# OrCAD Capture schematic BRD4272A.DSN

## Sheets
1 02: RF & Power: size A3; title: FG25 470 MHz 16 dBm Radio Board; rev: A02; company: Silicon Labs; note: BRD4272A
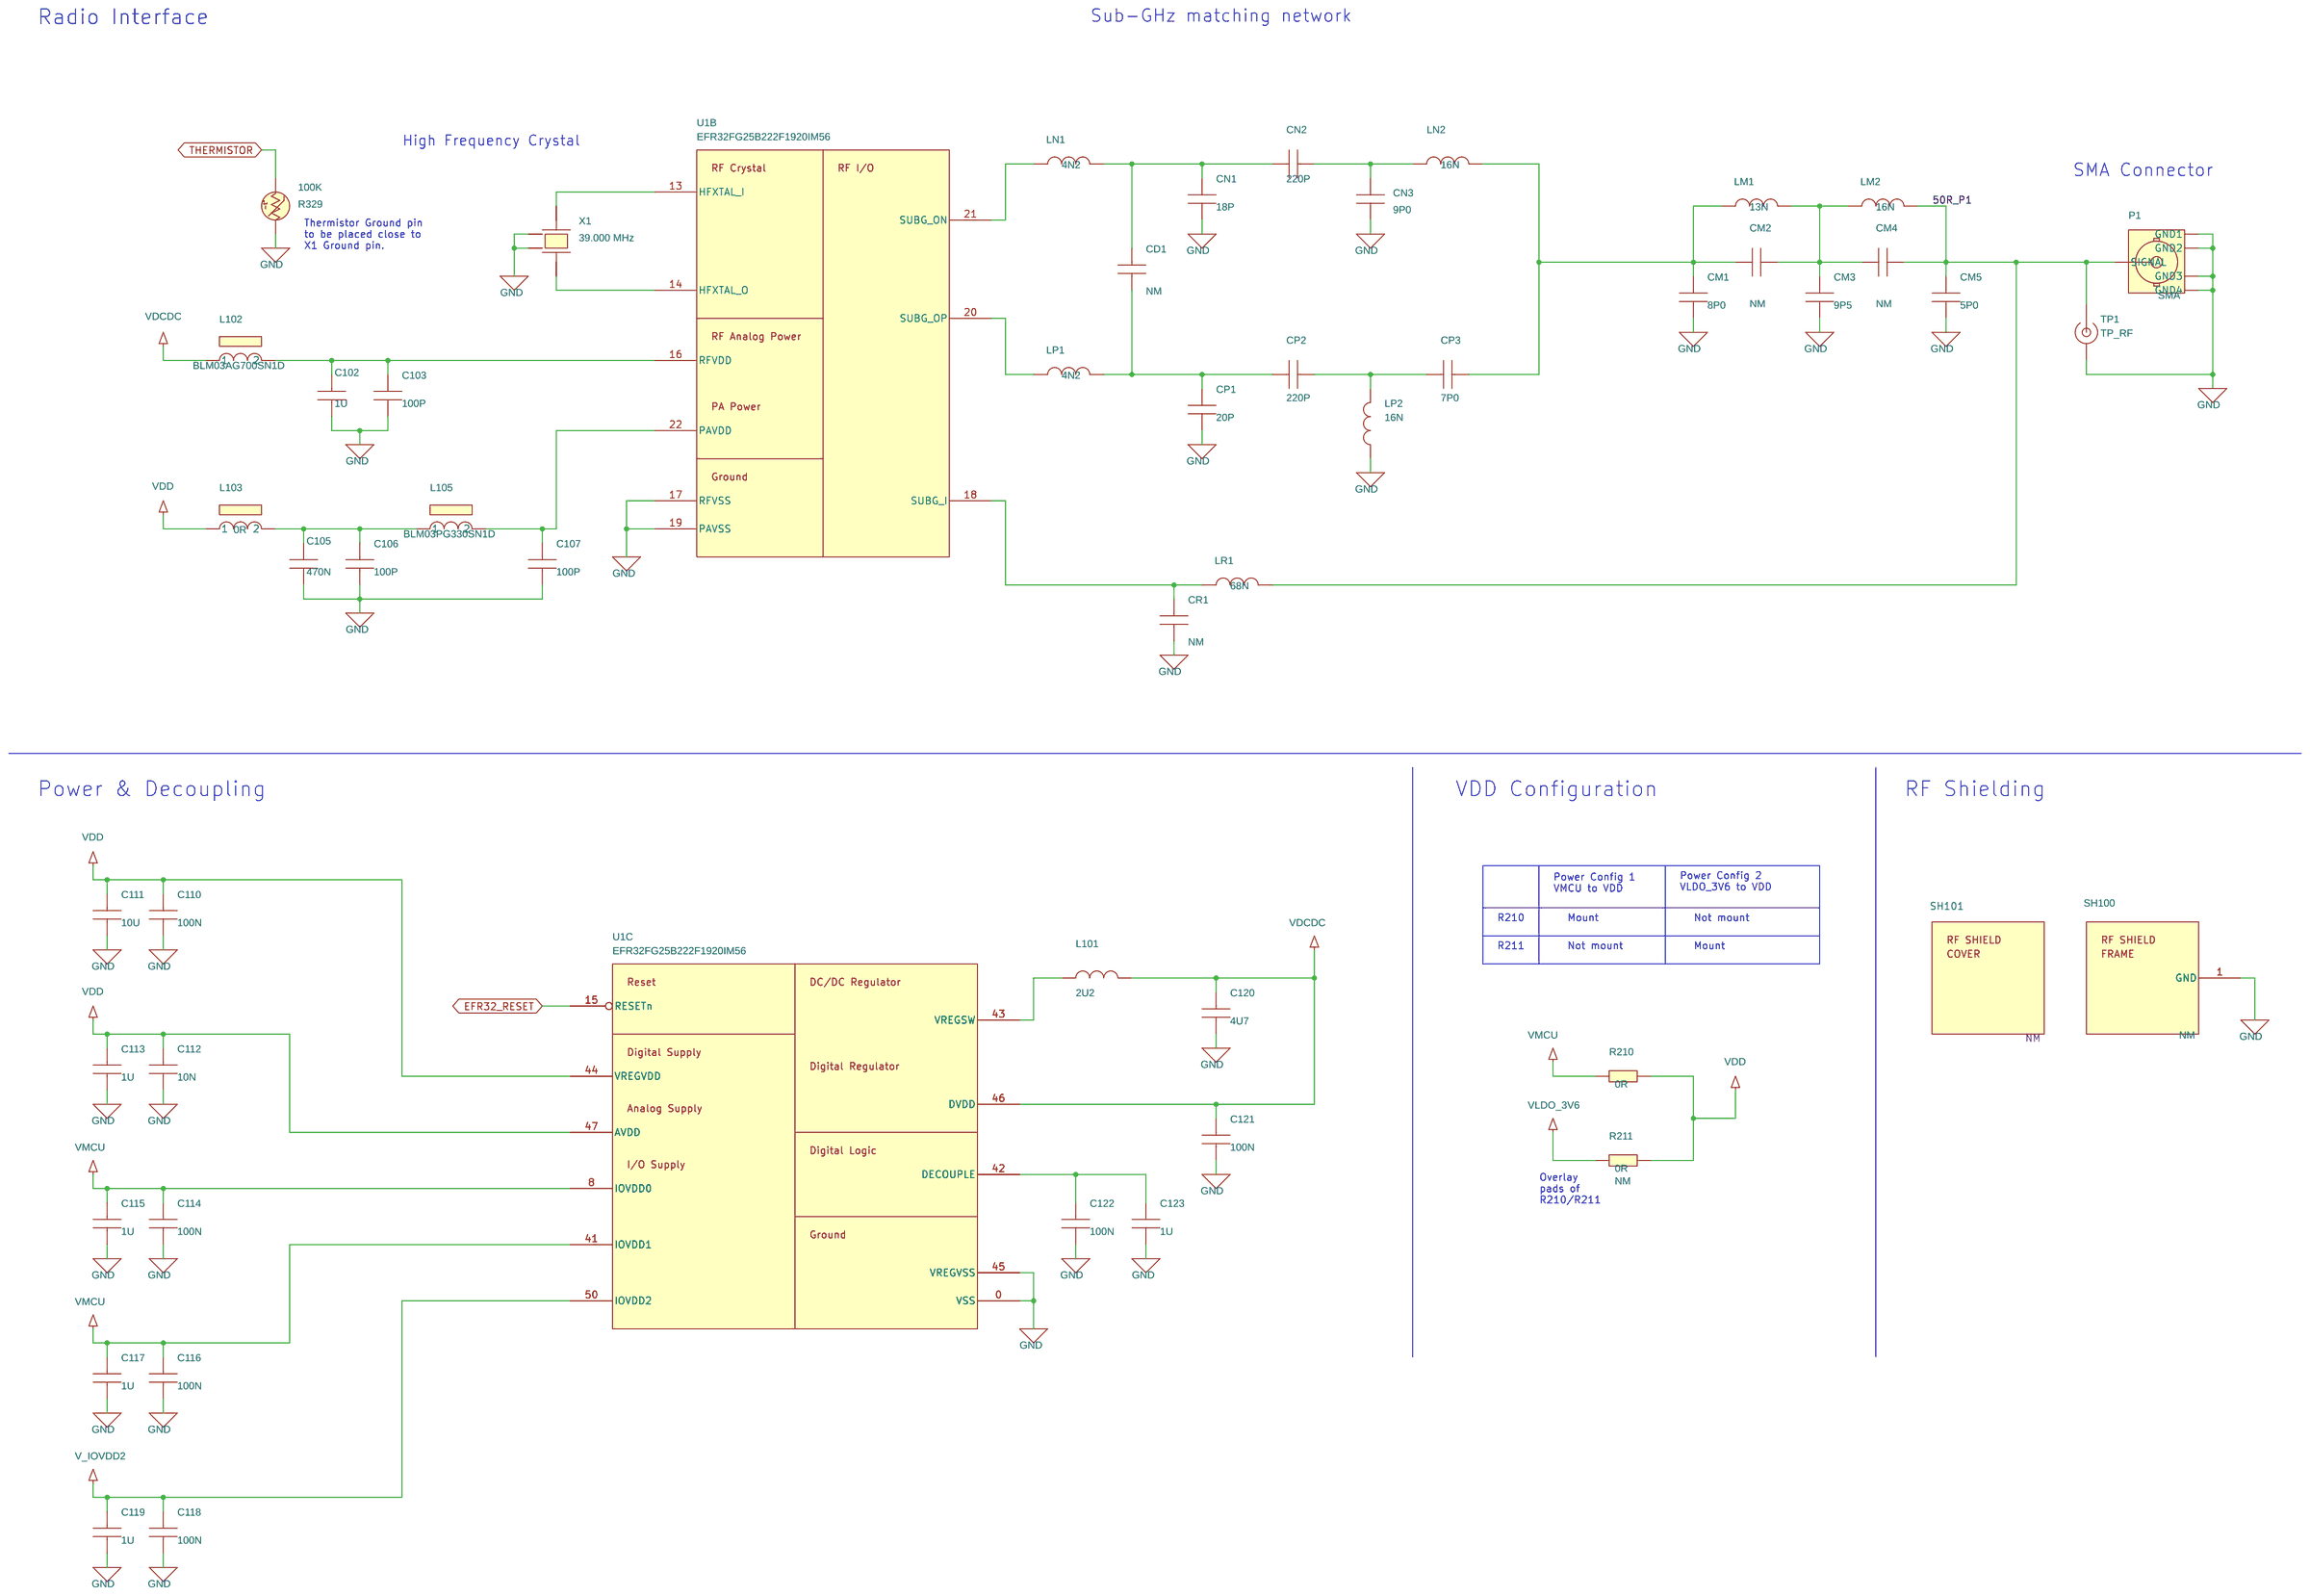
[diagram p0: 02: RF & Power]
2 01: Title Page
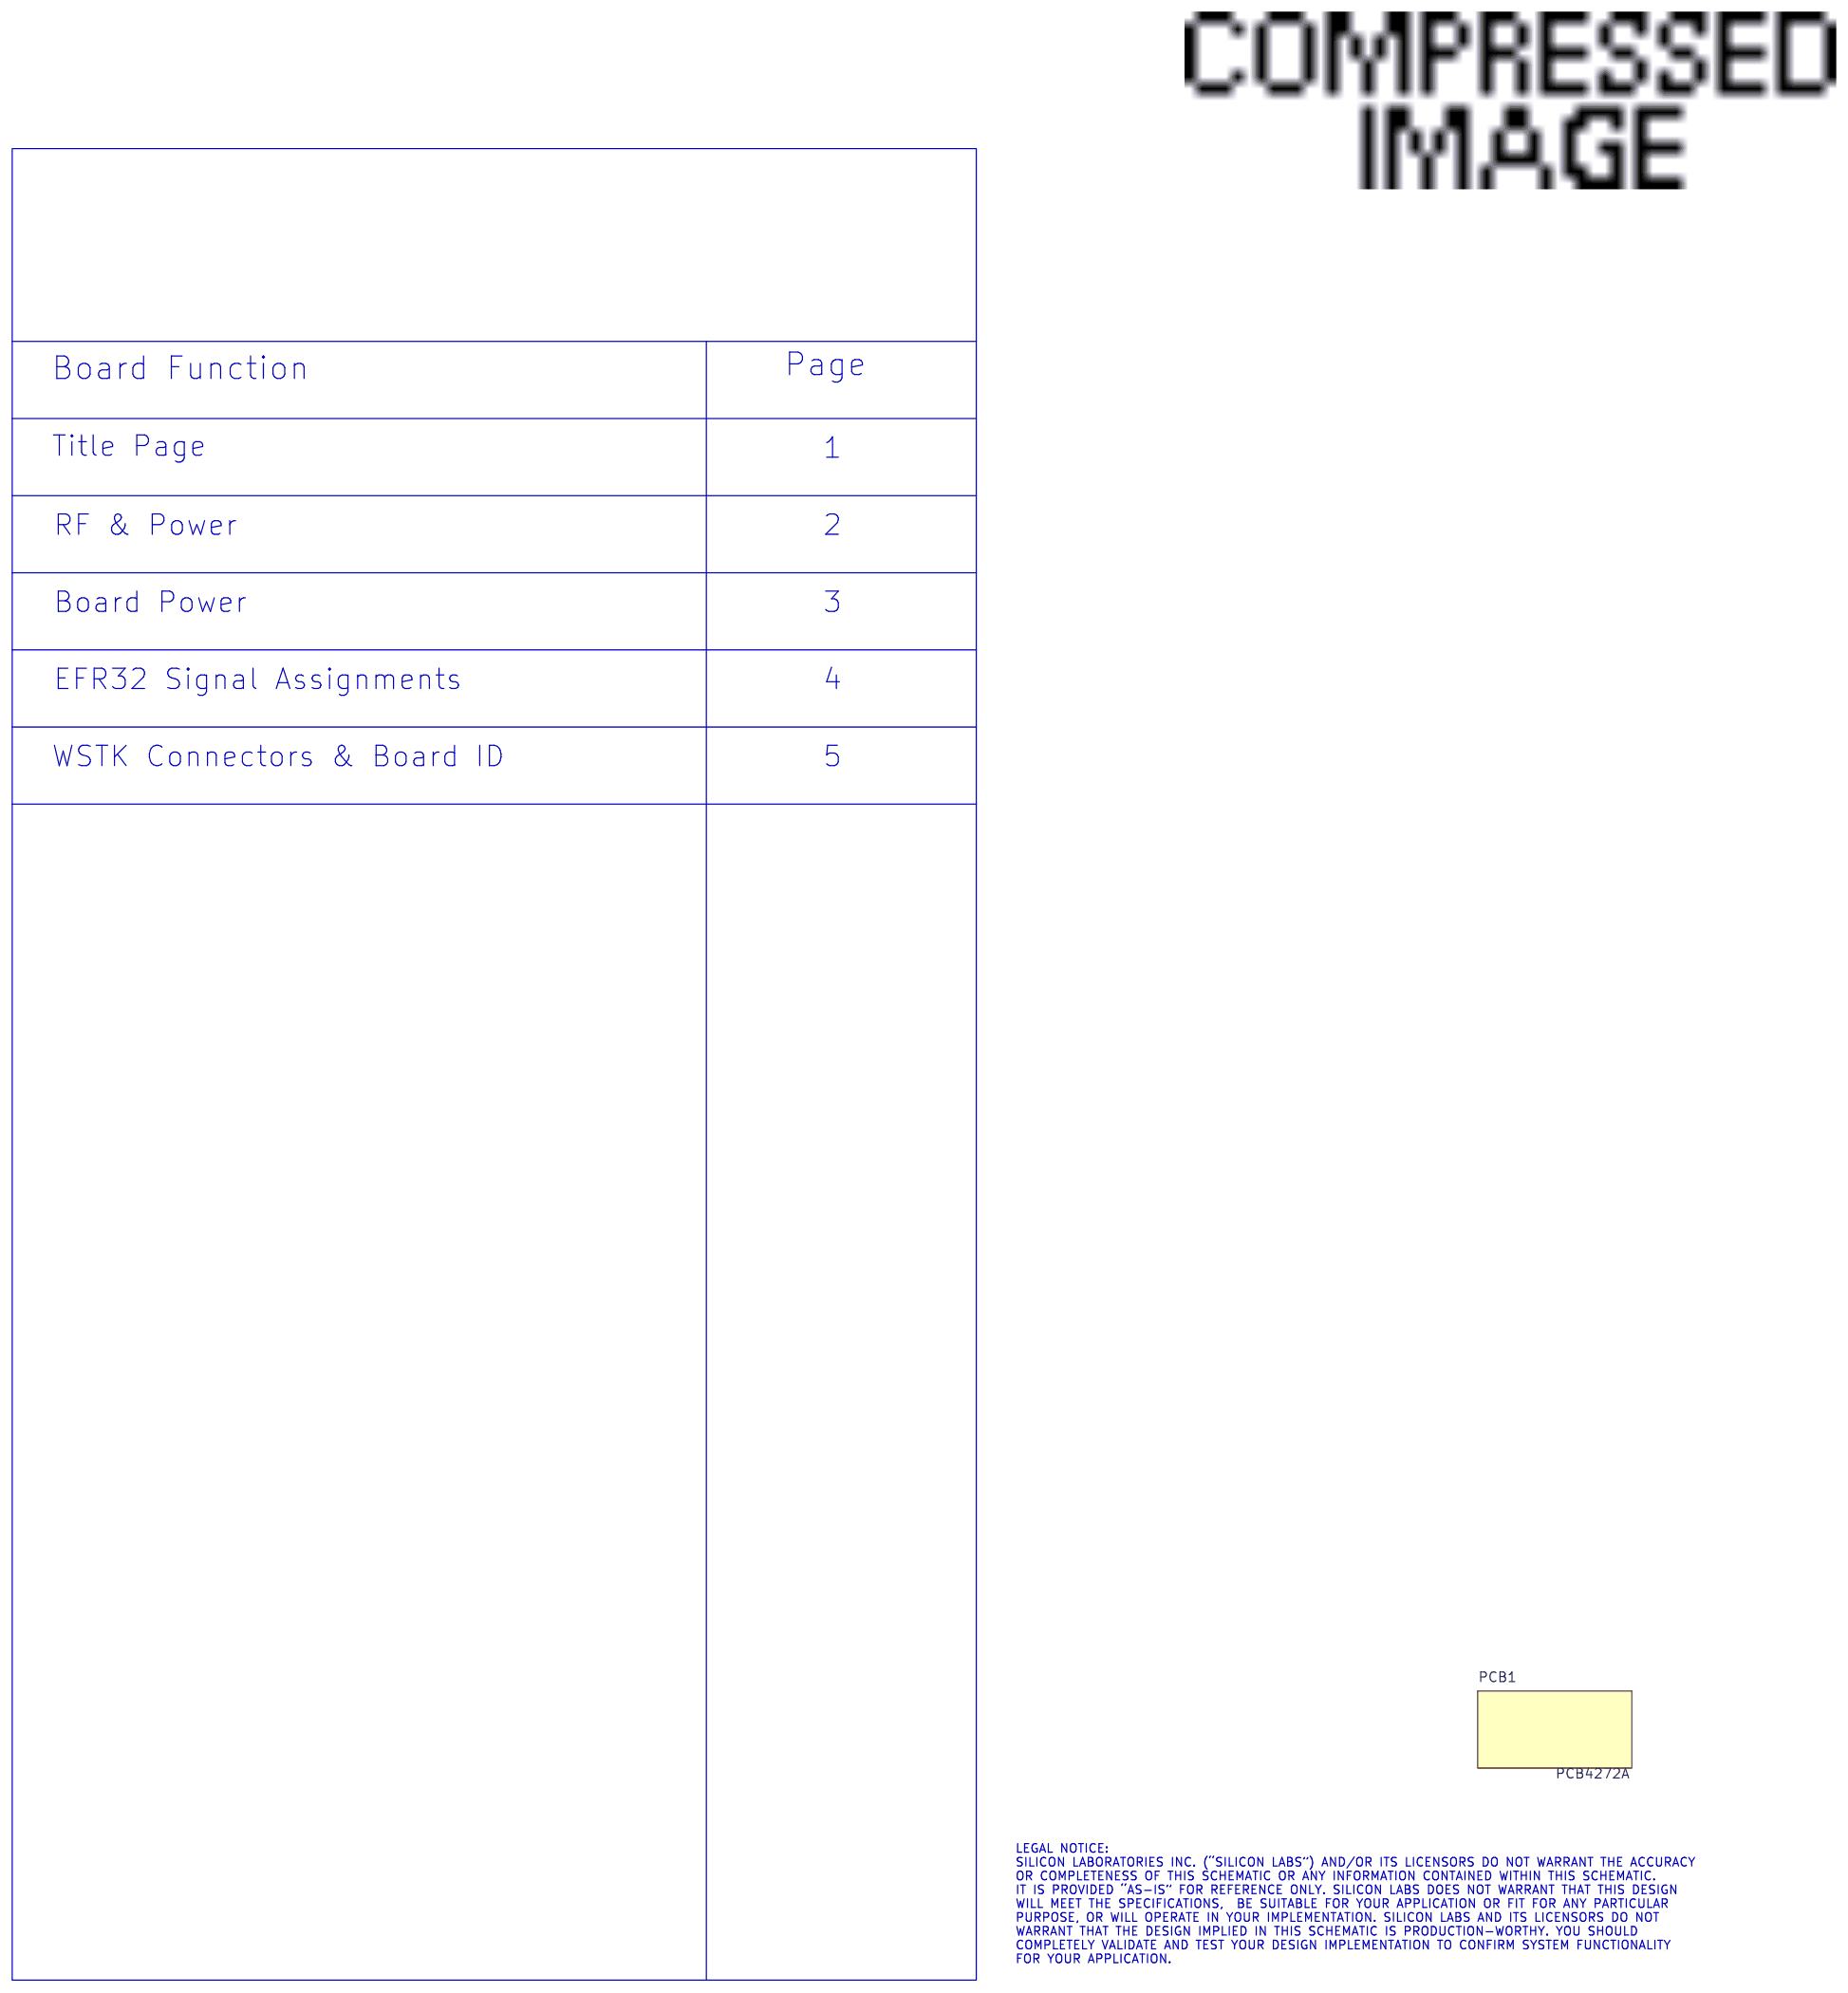
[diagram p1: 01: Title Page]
3 04: EFR32 Signal Assignments: size A3
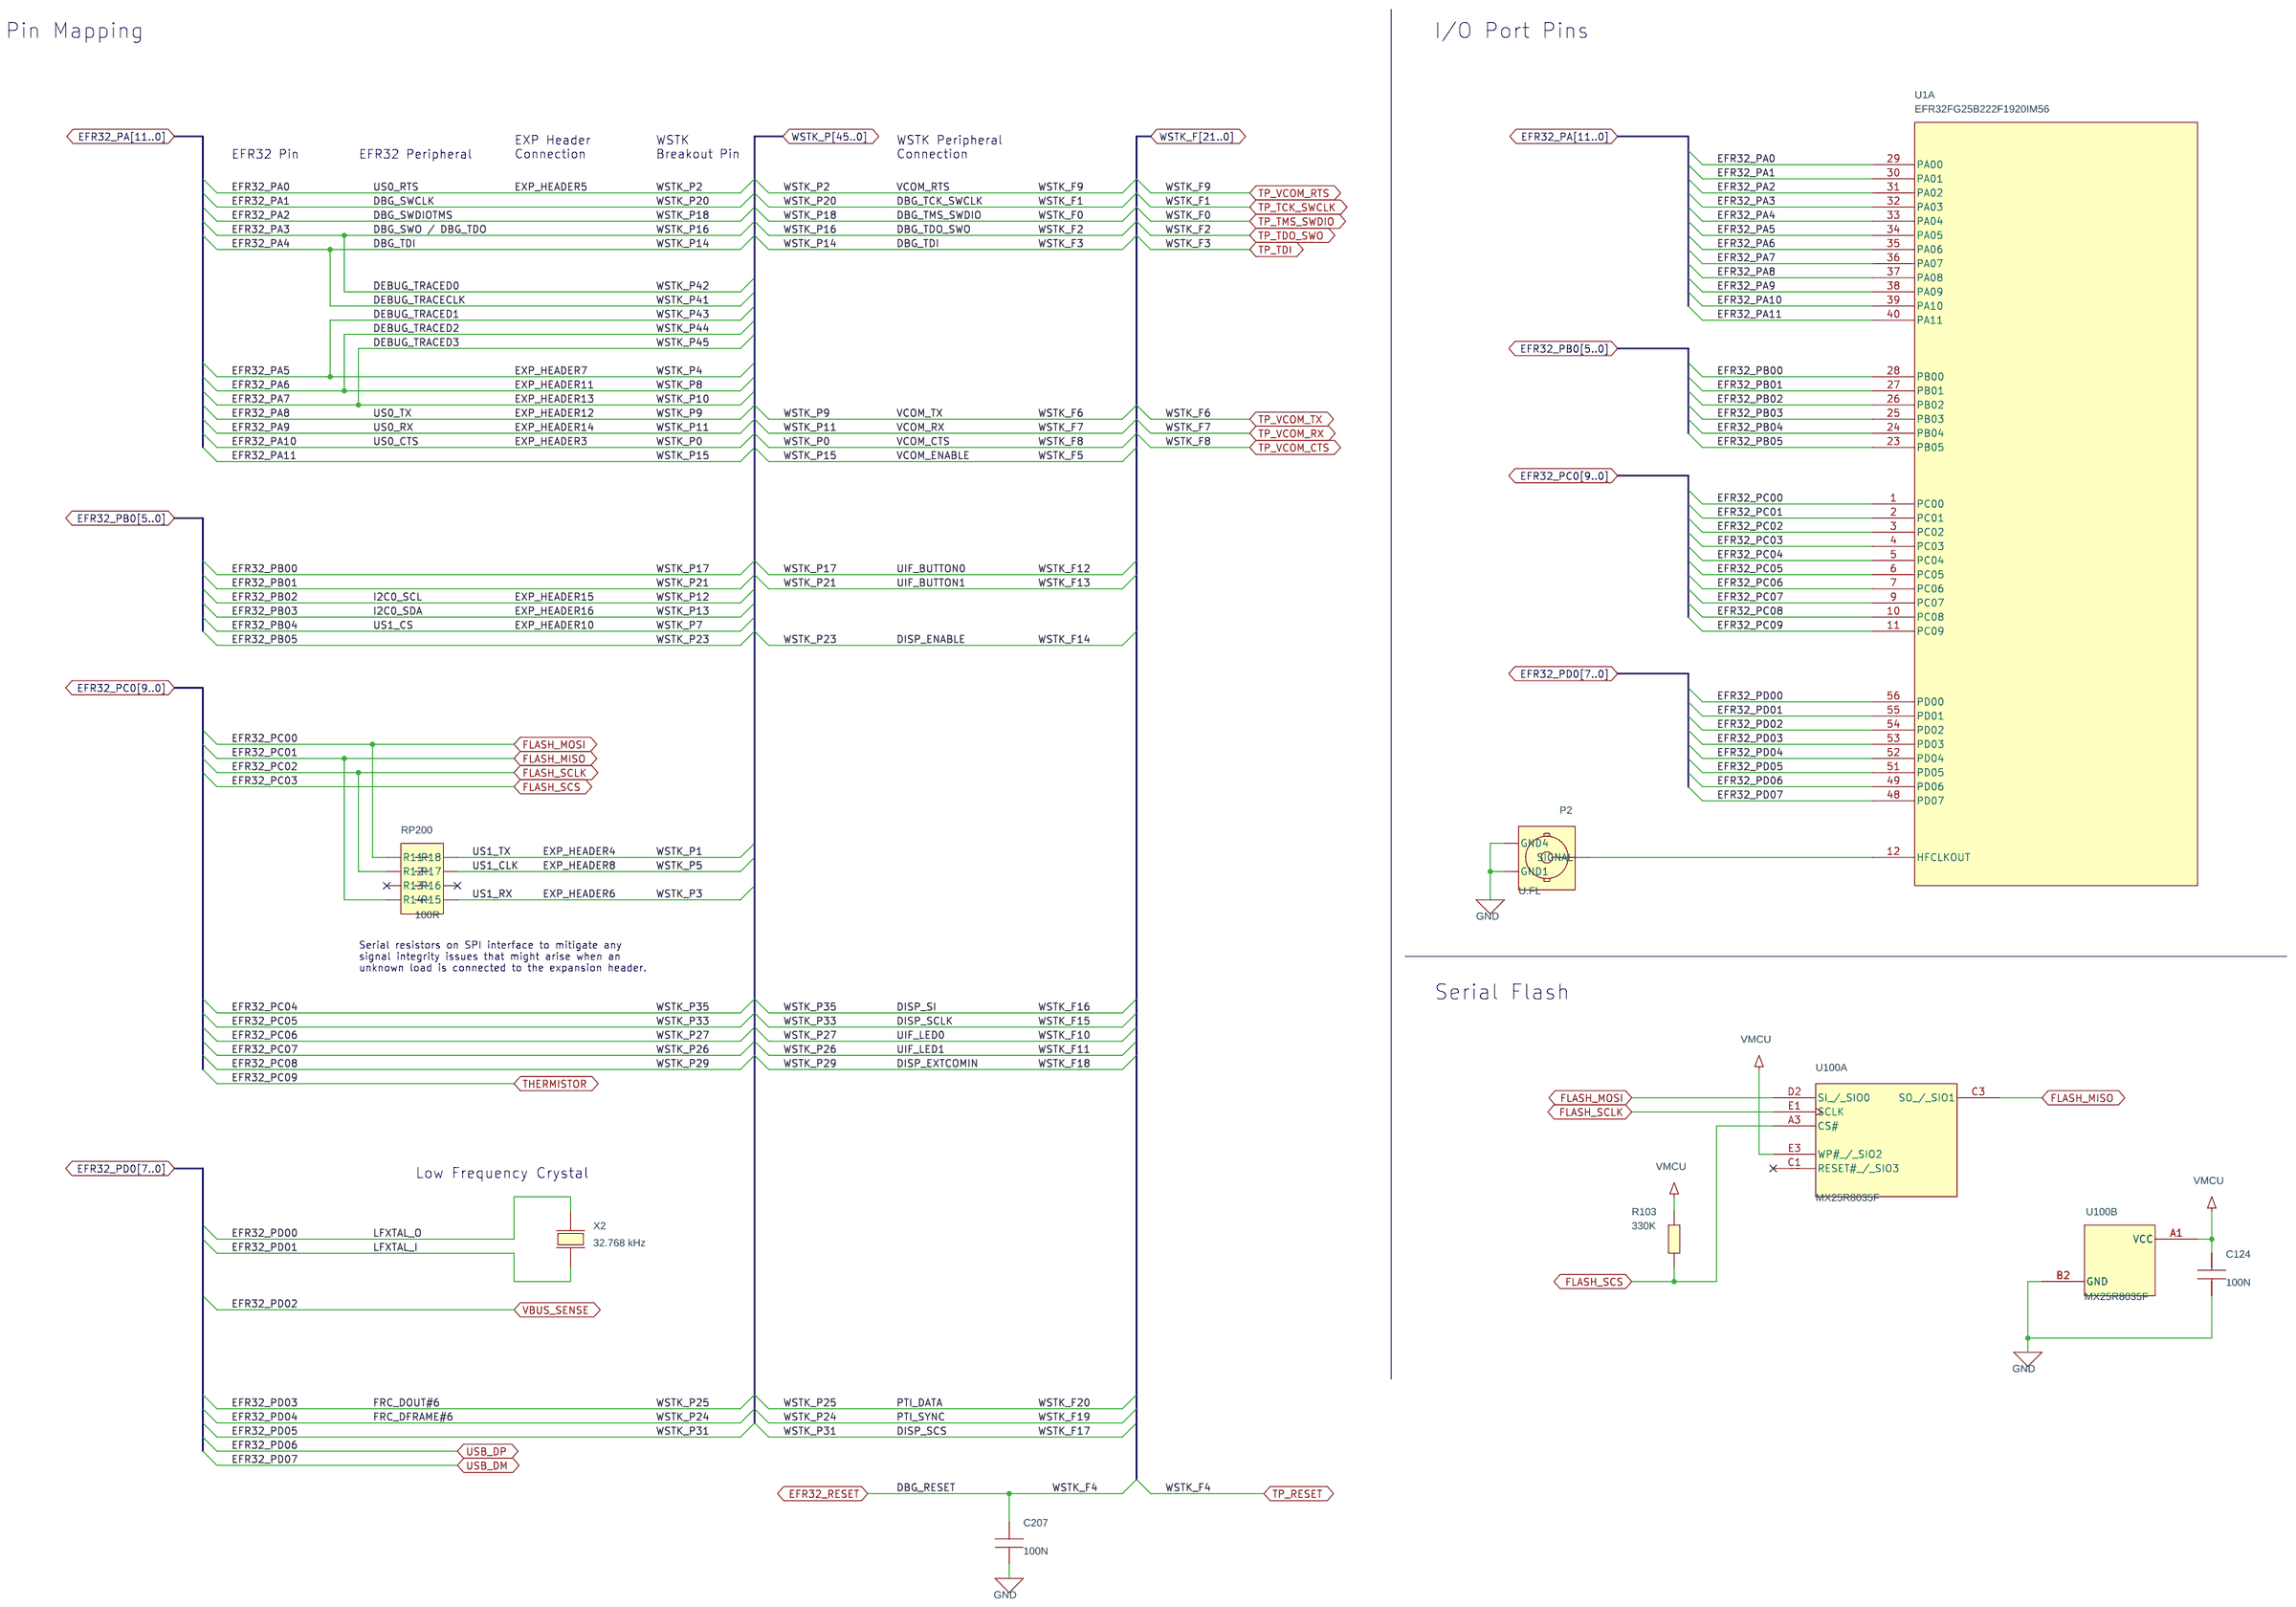
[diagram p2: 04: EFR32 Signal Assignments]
4 03: Board Power: size A3
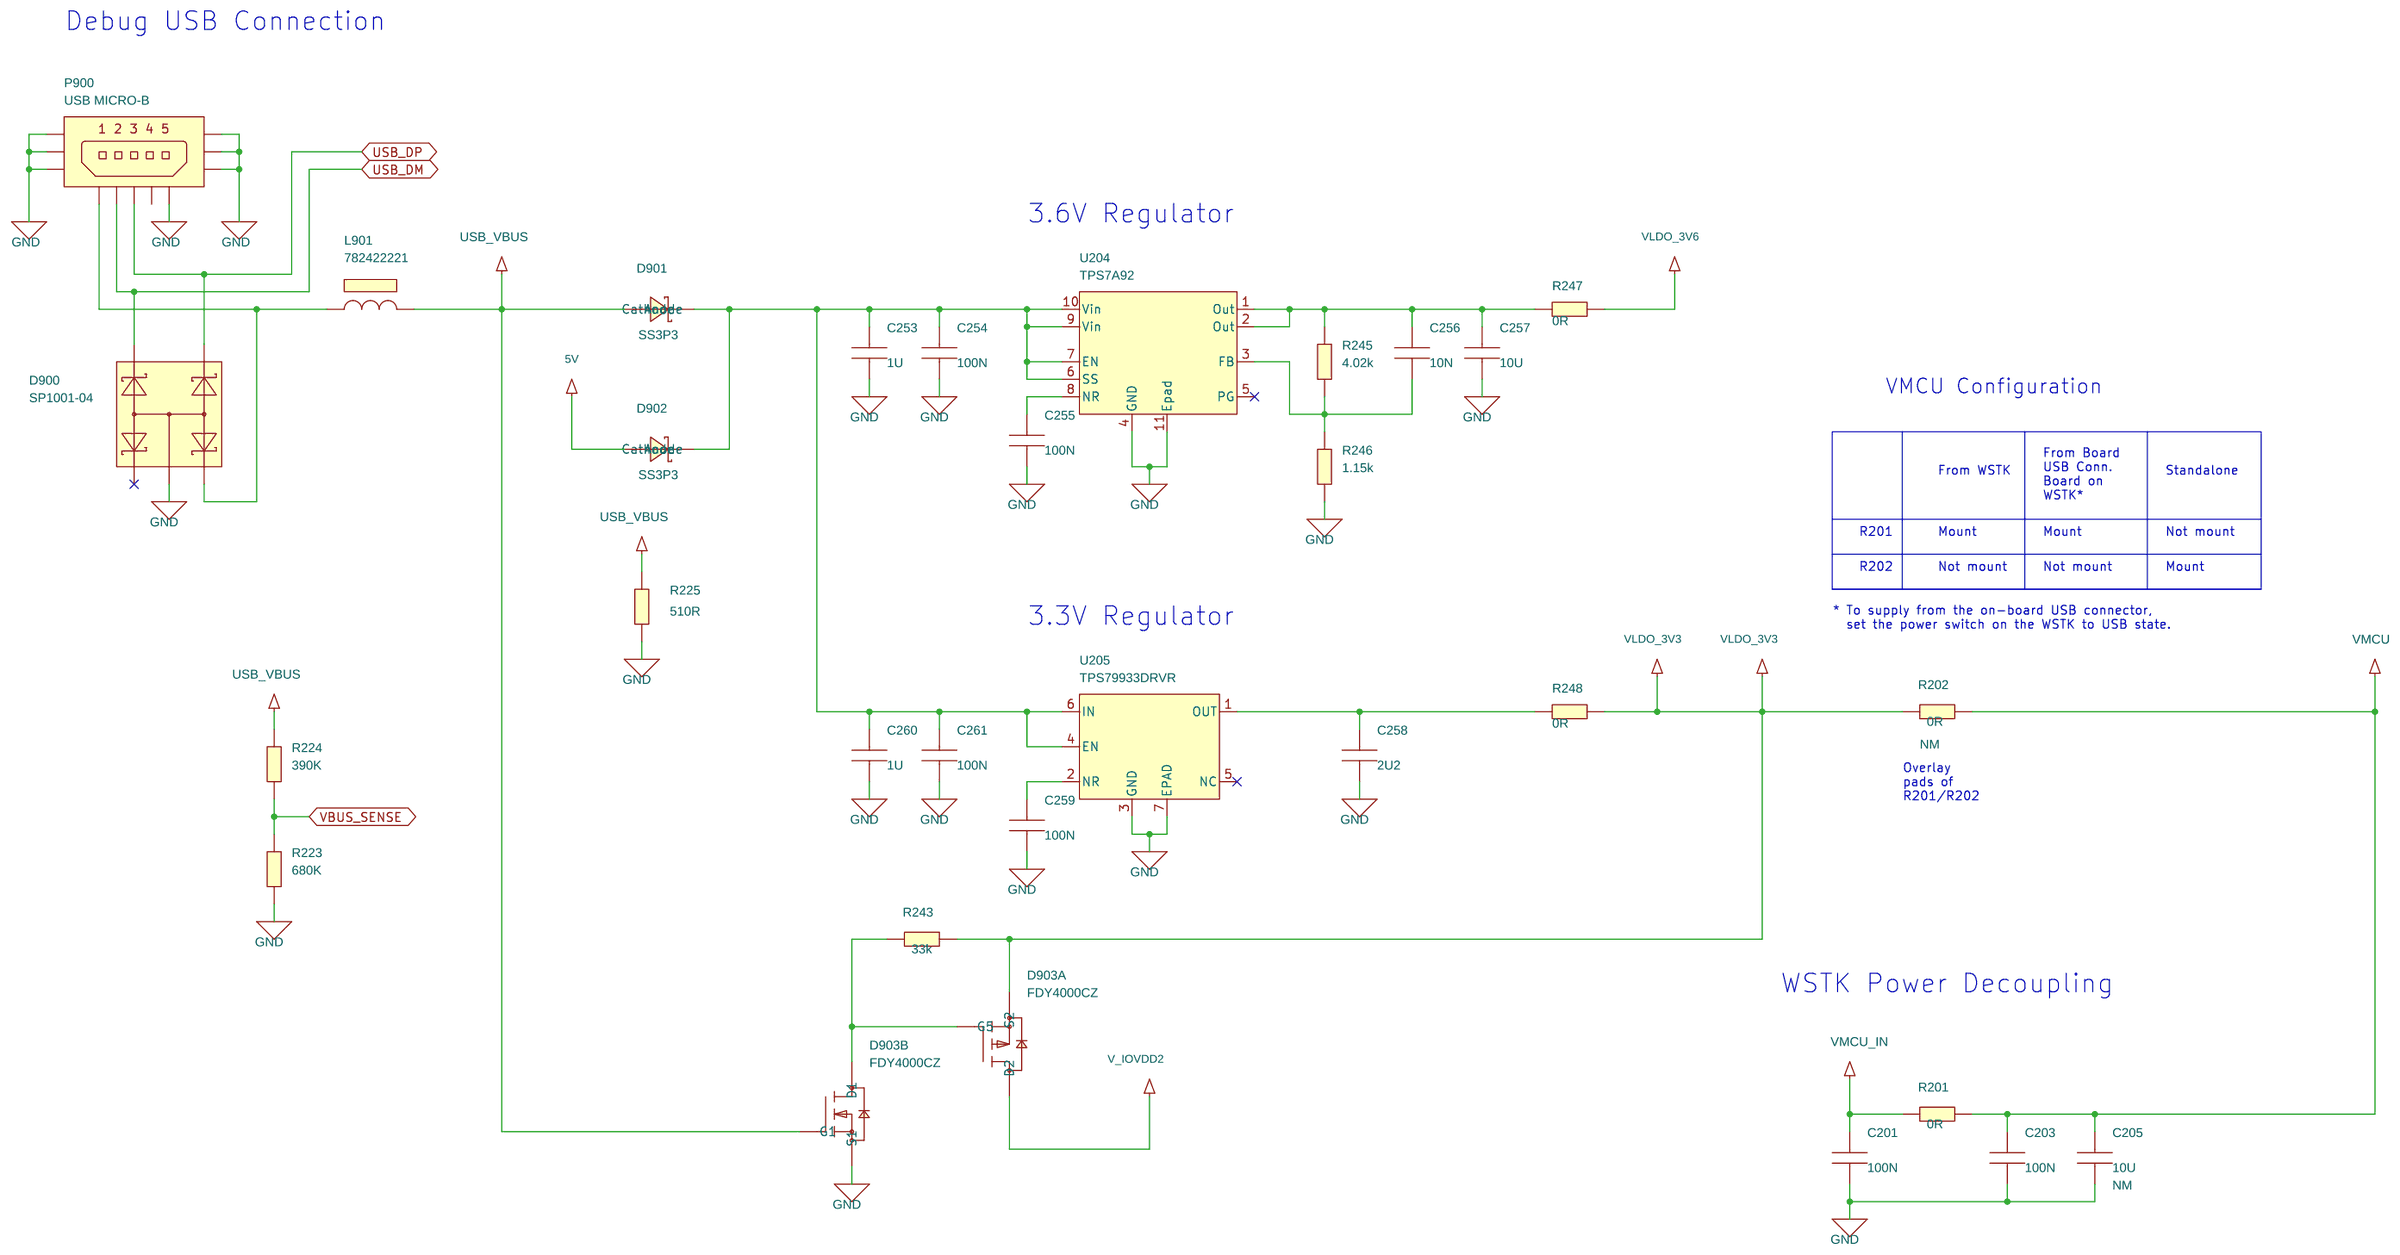
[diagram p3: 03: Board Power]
5 05: WSTK Connectors & Board ID: size A3
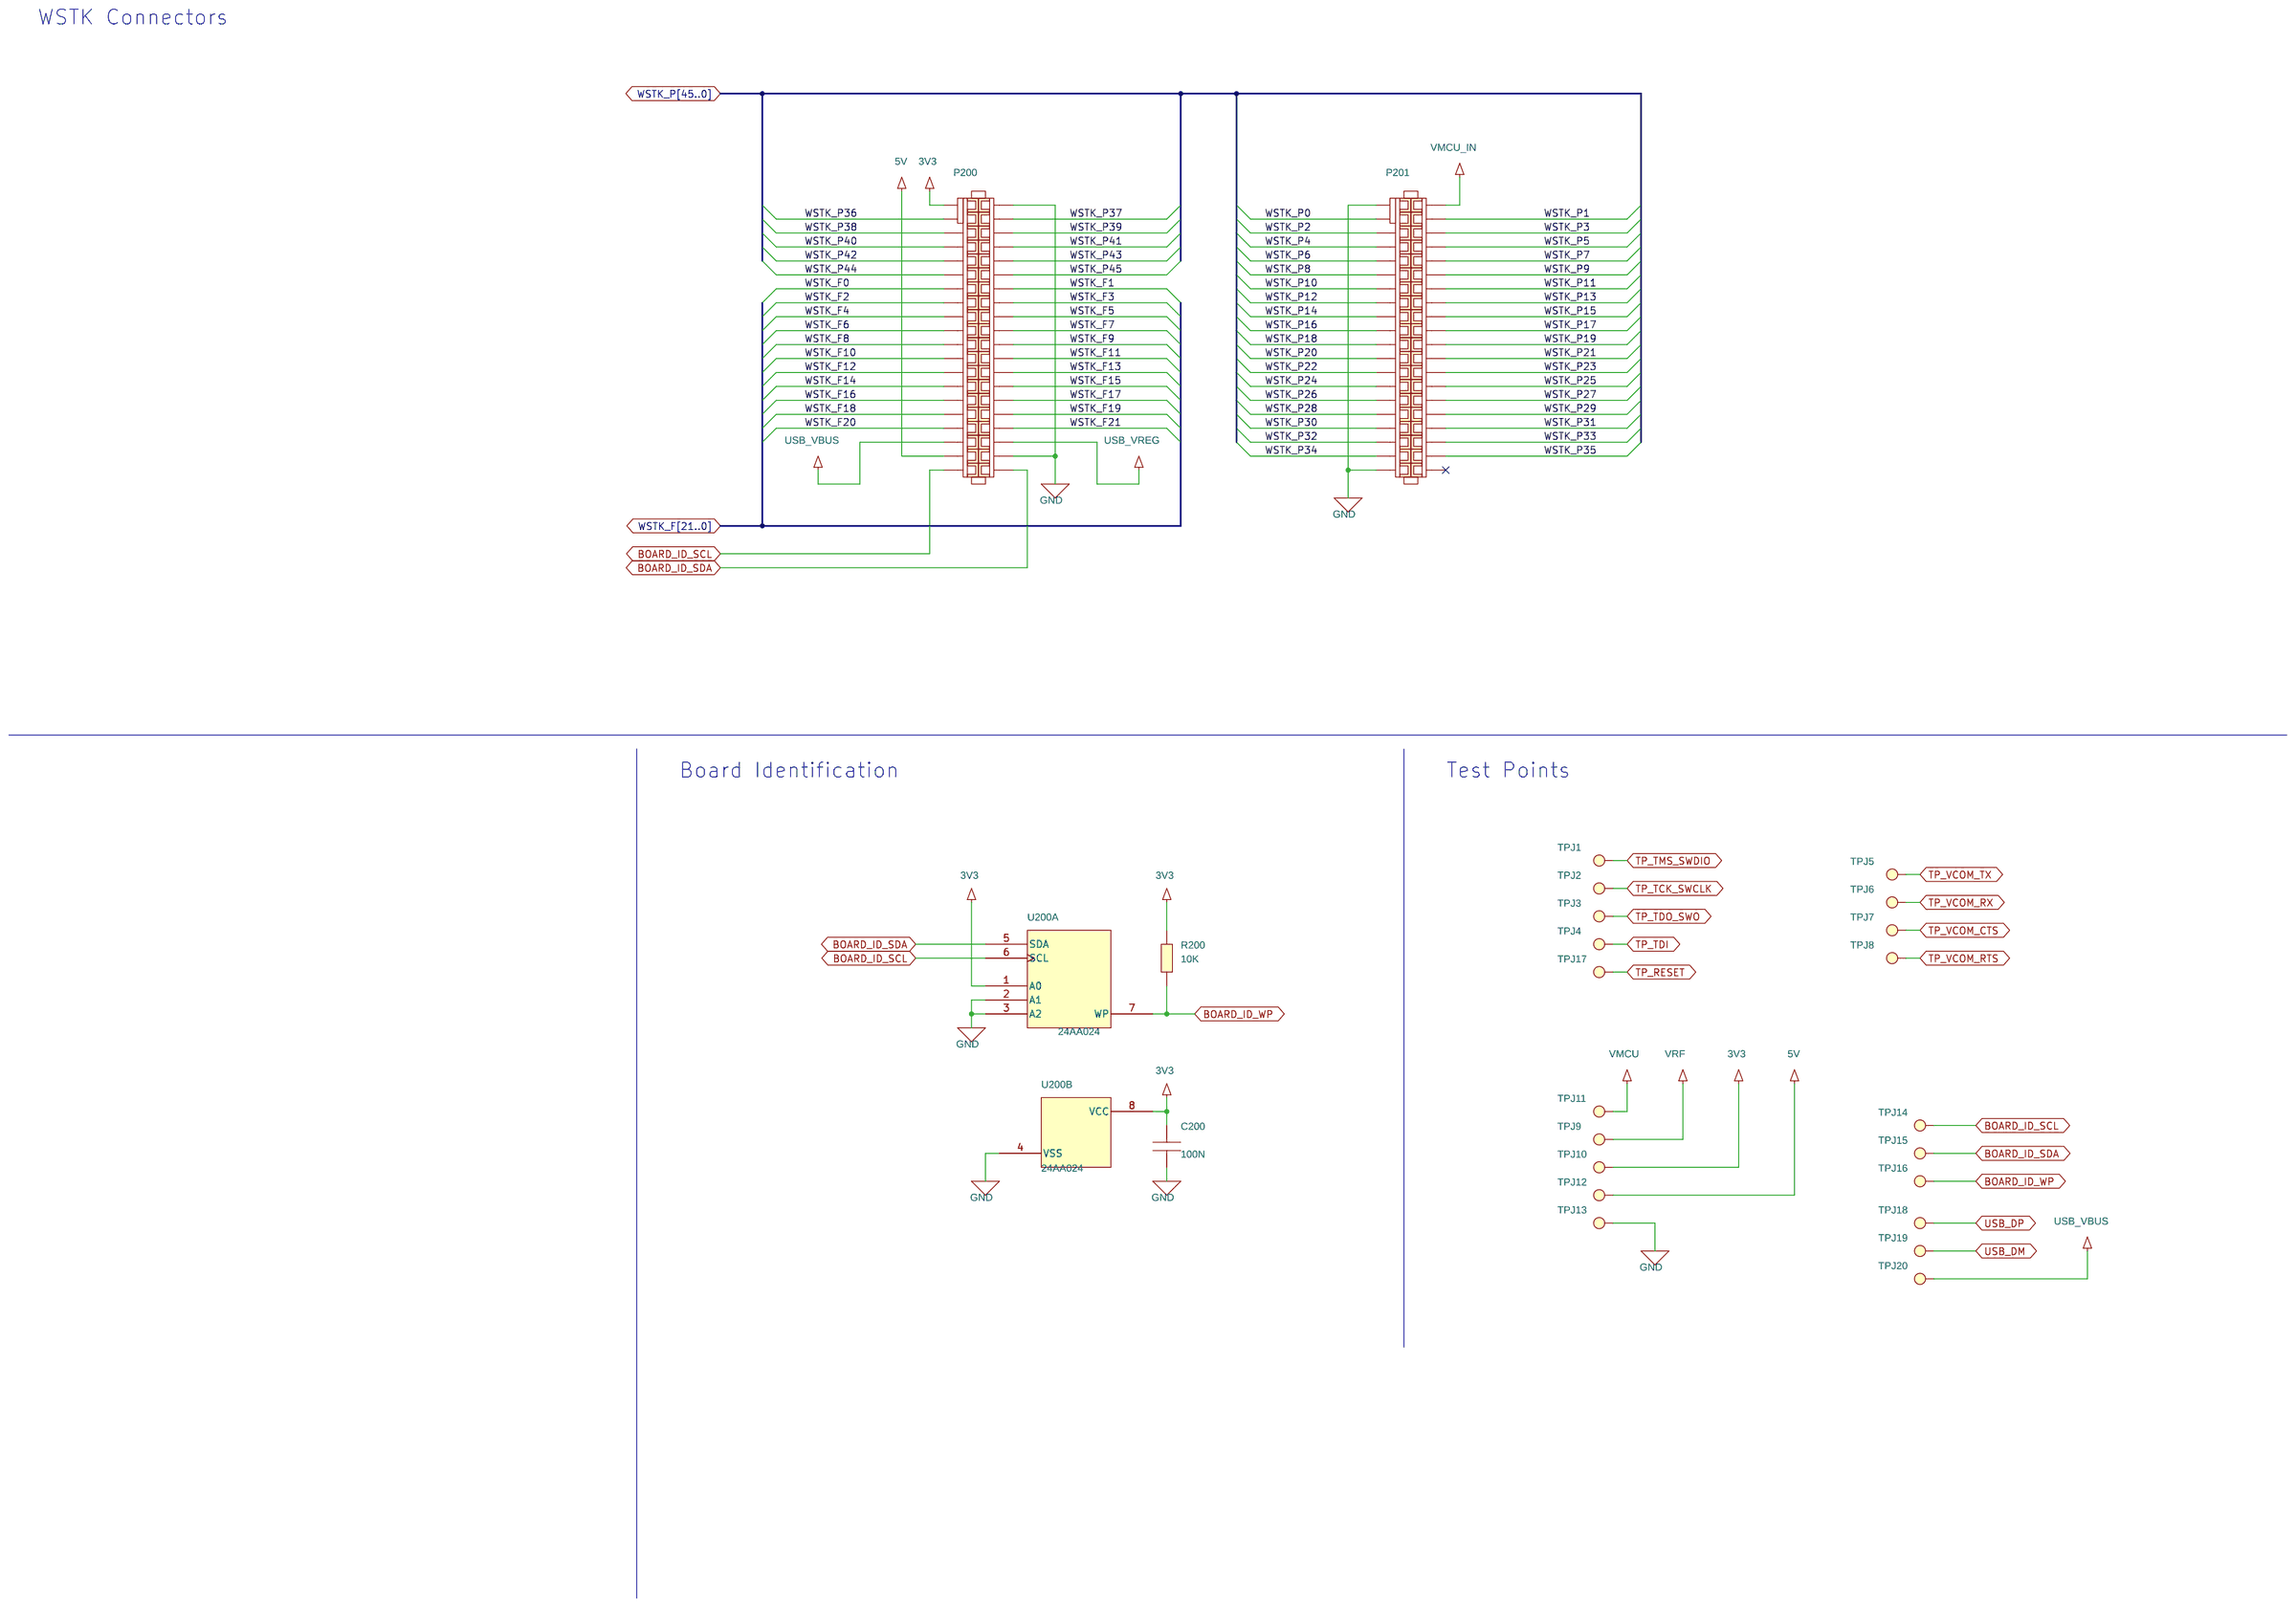
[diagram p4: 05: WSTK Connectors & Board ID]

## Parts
sheet 01: Title Page
PCB1  PCB4272A  [N/A]
sheet 02: RF & Power
C102  1U  [C0402_L]
C103  100P  [C0201_L]
C105  470N  [C0402_L]
C106  100P  [C0201_L]
C107  100P  [C0201_L]
C110  100N  [C0201_L]
C111  10U  [C0603_L]
C112  10N  [C0201_L]
C113  1U  [C0402_L]
C114  100N  [C0201_L]
C115  1U  [C0402_L]
C116  100N  [C0201_L]
C117  1U  [C0402_L]
C118  100N  [C0201_L]
C119  1U  [C0402_L]
C120  4U7  [C0603_L]
C121  100N  [C0201_L]
C122  100N  [C0201_L]
C123  1U  [C0402_L]
CD1  Unused  [C0201_L]
CM1  8P0  [C0201_L]
CM2  Unused  [C0201_L]
CM3  9P5  [C0201_L]
CM4  Unused  [C0201_L]
CM5  5P0  [C0201_L]
CN1  18P  [C0201_L]
CN2  220P  [C0201_L]
CN3  9P0  [C0201_L]
CP1  20P  [C0201_L]
CP2  220P  [C0201_L]
CP3  7P0  [C0201_L]
CR1  Unused  [C0201_L]
L101  2U2  [COIL_1008_L]
L102  BLM03AG700SN1D  [COIL_MUR_BLM03_0201]
L103  0R  [COIL_MUR_BLM03_0201]
L105  BLM03PG330SN1D  [COIL_MUR_BLM03_0201]
LM1  13N  [COIL_0201_L]
LM2  16N  [COIL_0201_L]
LN1  4N2  [COIL_0201_L]
LN2  16N  [COIL_0201_L]
LP1  4N2  [COIL_0201_L]
LP2  16N  [COIL_0201_L]
LR1  68N  [COIL_0201_L]
P1  SMA  [TE_SMA_1814832_TH_VER]
R210  0R  [R0402_L]
R211  0R  [R0402_L]
R329  100K  [R0201_L]
SH100  RF_SHIELD_FRAME_BMI-S-203-F  [LAIRD_BMI-S-203-F]
SH101  RF_SHIELD_COVER_BMI-S-203-C
TP1  TP_RF  [TP_INGUN_50_OHM_CLOSED openvia]
U1  EFR32FG25B222F1920IM56  [QFN56_M040_7.0X7.0_EP_SL]  (sections A,B,C)
X1  39.000 MHz  [KDS_DSX211SH_2016]
sheet 03: Board Power
C201  100N  [C0201_L]
C203  100N  [C0201_L]
C205  10U  [C0805_L]
C253  1U  [C0402_L]
C254  100N  [C0201_L]
C255  100N  [C0201_L]
C256  10N  [C0201_L]
C257  10U  [C0402_L]
C258  2U2  [C0402_L]
C259  100N  [C0201_L]
C260  1U  [C0402_L]
C261  100N  [C0201_L]
D900  SP1001-04  [SOT553_L]
D901  SS3P3  [DO-220AA]
D902  SS3P3  [DO-220AA]
D903  FDY4000CZ  [SOT-563]  (sections A,B)
L901  782422221  [COIL_0402]
P900  USB MICRO-B  [KLS_L-KLS1-238-0-X-0-X]
R201  0R  [R0402_L]
R202  0R  [R0402_L]
R223  680K  [R0201_L]
R224  390K  [R0201_L]
R225  510R  [R0603_L]
R243  33k  [R0402_L]
R245  4.02k  [R0201_L]
R246  1.15k  [R0201_L]
R247  0R  [R0603_L]
R248  0R  [R0603_L]
U204  TPS7A92  [WFDFN-10_EP_TPS7A92]
U205  TPS79933DRVR  [SON-6_EP_TPS79933DDCR]
sheet 04: EFR32 Signal Assignments
C124  100N  [C0201_L]
C207  100N  [C0201_L]
P2  U.FL  [HIROSE_U.FL-R-SMT-1]
R103  330K  [R0201_L]
RP200  100R  [RES_MNR04-8]
U100  MX25R8035F  [BGA8_M040_1.24x1.75_WLCSP]  (sections A,B)
X2  32.768 kHz  [X_MCS_CM8V-T1A]
sheet 05: WSTK Connectors & Board ID
C200  100N  [C0201_L]
P200  SOCKET_WCON_2X20_1.27MM_SMD  [SAM_SFC-120-T2-D-A-2X20_SNUM]
P201  SOCKET_WCON_2X20_1.27MM_SMD  [SAM_SFC-120-T2-D-A-2X20_SNUM]
R200  10K  [R0201_L]
TPJ1  TPJ_SMD  [TP_1.0_SMD]
TPJ2  TPJ_SMD  [TP_1.0_SMD]
TPJ3  TPJ_SMD  [TP_1.0_SMD]
TPJ4  TPJ_SMD  [TP_1.0_SMD]
TPJ5  TPJ_SMD  [TP_1.0_SMD]
TPJ6  TPJ_SMD  [TP_1.0_SMD]
TPJ7  TPJ_SMD  [TP_1.0_SMD]
TPJ8  TPJ_SMD  [TP_1.0_SMD]
TPJ9  TPJ_SMD  [TP_1.0_SMD]
TPJ10  TPJ_SMD  [TP_1.0_SMD]
TPJ11  TPJ_SMD  [TP_1.0_SMD]
TPJ12  TPJ_SMD  [TP_1.0_SMD]
TPJ13  TPJ_SMD  [TP_1.0_SMD]
TPJ14  TPJ_SMD  [TP_1.0_SMD]
TPJ15  TPJ_SMD  [TP_1.0_SMD]
TPJ16  TPJ_SMD  [TP_1.0_SMD]
TPJ17  TPJ_SMD  [TP_1.0_SMD]
TPJ18  TPJ_SMD  [TP_1.0_SMD]
TPJ19  TPJ_SMD  [TP_1.0_SMD]
TPJ20  TPJ_SMD  [TP_1.0_SMD]
U200  24AA024  [TDFN8_M050_2.0X3.0_EP]  (sections A,B)

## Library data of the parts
PCB1 = PCB: Mfg #: PCB4272A Rev. A02; Price_1K: 1.25
C102 C113 C115 C117 C119 C123 C253 C260 = C0402: Rating: 6.3V; Technology: X7R; Tolerance: 10%
C103 C106 C107 = C0201: Rating: 25V; Technology: C0G; Tolerance: 5%
C105 = C0402: Rating: 10V; Technology: X7R; Tolerance: 10%
C110 C114 C116 C118 C121 C122 C124 C200 C201 C203 C207 C254 C255 C259 C261 = C0201: Rating: 16V; Technology: X7S; Tolerance: 20%
C111 = C0603: Rating: 6.3V; Technology: X7R; Tolerance: 20%
C112 C256 = C0201: Rating: 16V; Technology: X7R; Tolerance: 10%
C120 = C0603: Rating: 6.3V; Technology: X7R; Tolerance: 10%
CD1 CM2 CM4 CR1 = C0201: Not Mounted: NM; Technology: C0G
CM1 = C0201: Mfg: Murata; Mfg #: GRM0335C1H8R0WA01D; Technology: C0G; Tolerance: ±0.05P
CM3 = C0201: Mfg: Murata; Mfg #: GRM0335C1H9R5WA01D; Technology: C0G; Tolerance: ±0.05P
CM5 = C0201: Mfg: Murata; Mfg #: GRM0335C1H5R0WA01D; Technology: C0G; Tolerance: ±0.05P
CN1 = C0201: Mfg: Murata; Mfg #: GRM0335C1H180GA01D; Technology: C0G; Tolerance: ±2%
CN2 CP2 = C0201: Mfg: Murata; Mfg #: GRM0335C1H221GA01D; Technology: C0G; Tolerance: ±2%
CN3 = C0201: Mfg: Murata; Mfg #: GRM0335C1H9R0WA01D; Technology: C0G; Tolerance: ±0.05P
CP1 = C0201: Mfg: Murata; Mfg #: GRM0335C1H200GA01D; Technology: C0G; Tolerance: ±2%
CP3 = C0201: Mfg: Murata; Mfg #: GRM0335C1H7R0WA01D; Technology: C0G; Tolerance: ±0.05P
L101 = L1008: Mfg: Murata; Mfg #: DFE2HCAH2R2MJ0L; Tolerance: +/-20%
L102 = BLM03AX
L103 = BLM03AX_1
L105 = BLM03AX_2
LM1 = L0201: Mfg: Murata; Mfg #: LQP03HQ13NH02D; Tolerance: ±3%
LM2 LN2 LP2 = L0201: Mfg: Murata; Mfg #: LQP03HQ16NH02D; Tolerance: ±3%
LN1 LP1 = L0201: Mfg: Murata; Mfg #: LQP03HQ4N2B02D; Tolerance: ±0.1N
LR1 = L0201: Mfg: Murata; Mfg #: LQP03HQ68NH02D; Tolerance: ±3%
P1 = SMA_TH_WELLSHOW
R201 R210 R243 = R0402
R202 R211 = R0402: Not Mounted: NM
R329 = THERMISTOR_0201
SH100 = RF_SHIELD_FRAME_BMI-S-203-F: Not Mounted: NM
SH101 = RF_SHIELD_COVER_BMI-S-203-C: Not Mounted: NM
TP1 = TP_RF
U1 = EFR32xG25_QFN56_HFCLKOUT: Mfg #: EFR32FG25B222F1920IM56-BR
X1 = DSX211SH: Mfg: TXC; Mfg #: 8Y39072003; Price_1K: 0.512
C205 = CAPACITOR: Not Mounted: NM; Technology: X7R
C257 = C0402: Rating: 6.3V; Technology: X6S; Tolerance: 20%
C258 = C0402: Rating: 6.3V; Technology: X7S; Tolerance: 10%
D900 = SP1001-04: Price_1K: 0.187
D901 D902 = SS3P3
D903 = FDY4000CZ
L901 = WE-CBA: Mfg: Würth Elektronik
P900 = KLS_L-KLS1-238-0-0-0
R103 R200 R223 R224 R245 R246 = R0201
R225 R247 R248 = R0603
U204 = TPS7A92: Mfg #: TPS7A9201DSKR
U205 = TPS79933DRVR
P2 = KLS_U.FL
RP200 = MNR04M0APJ101
U100 = MX25R8035
X2 = CM8V-T1A: Mfg: Micro Crystal AG; Mfg #: CM8V-T1A-32.768KHZ-7PF-20PPM-TA-QC
P200 P201 = SOCKET_WCON_2X20_1.27MM_SMD: Mfg #: 2344-220MS3CUNR6
TPJ1-TPJ20 = TPJ_SMD
U200 = M24C02: CONTEC Footprint: MSOP8_M065_W3.0; Mfg: Microchip; Mfg #: 24AA024T-I/MNY; Price_1K: 0.06

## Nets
3V3: C200.1 P200.1 R200.2 TPJ10.1(TP) U200.1(A0) U200.8(VCC)
5V: D902.2(Anode) P200.37 TPJ12.1(TP)
GND: C102.2 C103.2 C105.2 C106.2 C107.2 C110.2 C111.2 C112.2 C113.2 C114.2 C115.2 C116.2 C117.2 C118.2 C119.2 C120.2 C121.2 C122.2 C123.2 C124.2 C200.2 C201.2 C203.2 C205.2 C207.2 C253.2 C254.2 C255.2 C257.2 C258.2 C259.2 C260.2 C261.2 CM1.2 CM3.2 CM5.2 CN1.2 CN3.1 CP1.2 CR1.2 D900.2 D903.1(S1) LP2.1 P1.2(GND1) P1.3(GND2) P1.4(GND3) P1.5(GND4) P2.2(GND1) P2.3(GND4) P200.2 P200.38 P201.1 P201.39 P900.5 P900.6 P900.7 P900.8 P900.9 P900.10 P900.11 R223.1 R225.1 R246.1 R329.2 SH100.1(GND) TP1.2(GND) TPJ13.1(TP) U1.0(VSS) U1.17(RFVSS) U1.19(PAVSS) U1.45(VREGVSS) U100.B2(GND) U200.2(A1) U200.3(A2) U200.4(VSS) U204.4(GND) U204.11(Epad) U205.3(GND) U205.7(EPAD) X1.2 X1.4
VDD: C110.1 C111.1 C112.1 C113.1 L103.1 R210.2 R211.2 U1.44(VREGVDD) U1.47(AVDD)
50R_P1: CM4.2 CM5.1 LM2.2 LR1.2 P1.1(SIGNAL) TP1.1(RF)
BOARD_ID_SCL: P200.39 TPJ14.1(TP) U200.6(SCL)
BOARD_ID_SDA: P200.40 TPJ15.1(TP) U200.5(SDA)
BOARD_ID_WP: R200.1 TPJ16.1(TP) U200.7(WP)
EFR32_PA0: P200.22 P201.5 TPJ8.1(TP) U1.29(PA00)
EFR32_PA1: P200.14 P201.23 TPJ2.1(TP) U1.30(PA01)
EFR32_PA2: P200.13 P201.21 TPJ1.1(TP) U1.31(PA02)
EFR32_PA3: P200.9 P200.15 P201.19 TPJ3.1(TP) U1.32(PA03)
EFR32_PA4: P200.8 P200.16 P201.17 TPJ4.1(TP) U1.33(PA04)
EFR32_PA5: P200.10 P201.7 U1.34(PA05)
EFR32_PA6: P200.11 P201.11 U1.35(PA06)
EFR32_PA7: P200.12 P201.13 U1.36(PA07)
EFR32_PA8: P200.19 P201.12 TPJ5.1(TP) U1.37(PA08)
EFR32_PA9: P200.20 P201.14 TPJ6.1(TP) U1.38(PA09)
EFR32_PA10: P200.21 P201.3 TPJ7.1(TP) U1.39(PA10)
EFR32_PA11: P200.18 P201.18 U1.40(PA11)
EFR32_PB00: P200.25 P201.20 U1.28(PB00)
EFR32_PB01: P200.26 P201.24 U1.27(PB01)
EFR32_PB02: P201.15 U1.26(PB02)
EFR32_PB03: P201.16 U1.25(PB03)
EFR32_PB04: P201.10 U1.24(PB04)
EFR32_PB05: P200.27 P201.26 U1.23(PB05)
EFR32_PC00: RP200.1(R11) U1.1(PC00) U100.D2(SI_/_SIO0)
EFR32_PC01: RP200.4(R14) U1.2(PC01) U100.C3(SO_/_SIO1)
EFR32_PC02: RP200.2(R12) U1.3(PC02) U100.E1(SCLK)
EFR32_PC03: R103.1 U1.4(PC03) U100.A3(CS#)
EFR32_PC04: P200.29 P201.38 U1.5(PC04)
EFR32_PC05: P200.28 P201.36 U1.6(PC05)
EFR32_PC06: P200.23 P201.30 U1.7(PC06)
EFR32_PC07: P200.24 P201.29 U1.9(PC07)
EFR32_PC08: P200.31 P201.32 U1.10(PC08)
EFR32_PC09: R329.1 U1.11(PC09)
EFR32_PD00: U1.56(PD00) X2.1
EFR32_PD01: U1.55(PD01) X2.2
EFR32_PD02: R223.2 R224.1 U1.54(PD02)
EFR32_PD03: P200.33 P201.28 U1.53(PD03)
EFR32_PD04: P200.32 P201.27 U1.52(PD04)
EFR32_PD05: P200.30 P201.34 U1.51(PD05)
EFR32_PD06: D900.4 P900.3 TPJ18.1(TP) U1.49(PD06)
EFR32_PD07: D900.5 P900.2 TPJ19.1(TP) U1.48(PD07)
EFR32_RESET: C207.1 P200.17 TPJ17.1(TP) U1.15(RESETn)
USB_VBUS: D901.2(Anode) D903.2(G1) L901.2 P200.35 R224.2 R225.2 TPJ20.1(TP)
USB_VREG: D903.4(S2) P200.36 R202.2 R243.1 R248.2
V_IOVDD2: C118.1 C119.1 D903.3(D2) U1.50(IOVDD2)
VDCDC: C120.1 C121.1 L101.2 L102.1 U1.46(DVDD)
VLDO_3V6: R211.1 R247.2
VMCU: C114.1 C115.1 C116.1 C117.1 C124.1 C203.1 C205.1 R103.2 R201.1 R202.1 R210.1 TPJ11.1(TP) U1.8(IOVDD0) U1.41(IOVDD1) U100.A1(VCC) U100.E3(WP#_/_SIO2)
VMCU_IN: C201.1 P201.2 R201.2
VRF: TPJ9.1(TP)
WSTK_F21: P200.34
WSTK_P1: P201.4 RP200.8(R18)
WSTK_P3: P201.6 RP200.5(R15)
WSTK_P5: P201.8 RP200.7(R17)
WSTK_P6: P201.9
WSTK_P19: P201.22
WSTK_P22: P201.25
WSTK_P28: P201.31
WSTK_P30: P201.33
WSTK_P32: P201.35
WSTK_P34: P201.37
WSTK_P36: P200.3
WSTK_P37: P200.4
WSTK_P38: P200.5
WSTK_P39: P200.6
WSTK_P40: P200.7
N17556723: C122.1 C123.1 U1.42(DECOUPLE)
N17556727: L101.1 U1.43(VREGSW)
N17618697: P2.1(SIGNAL) U1.12(HFCLKOUT)
N17621441: D900.3 L901.1 P900.1
N17622672: C256.2 R245.1 R246.2 U204.3(FB)
N17622674: C256.1 C257.1 R245.2 R247.1 U204.1(Out) U204.2(Out)
N17622750: C253.1 C254.1 C260.1 C261.1 D901.1(Cathode) D902.1(Cathode) U204.6(SS) U204.7(EN) U204.9(Vin) U204.10(Vin) U205.4(EN) U205.6(IN)
N17622769: C255.1 U204.8(NR)
N17643160: D903.5(G5) D903.6(D1) R243.2
N17648422: C258.1 R248.1 U205.1(OUT)
N17652382: C259.1 U205.2(NR)
N17758206: CM2.2 CM3.1 CM4.1 LM1.2 LM2.1
N17758241: CM1.1 CM2.1 CP3.1 LM1.1 LN2.2
N17758340: LN1.1 U1.21(SUBG_ON)
N17758346: LP1.1 U1.20(SUBG_OP)
N17758372: C102.1 C103.1 L102.2 U1.16(RFVDD)
N17758436: C107.1 L105.2 U1.22(PAVDD)
N17758469: C105.1 C106.1 L103.2 L105.1
N17758534: U1.13(HFXTAL_I) X1.3
N17758549: U1.14(HFXTAL_O) X1.1
N17758602: CR1.1 LR1.1 U1.18(SUBG_I)
N17776329: CD1.1 CN1.1 CN2.1 LN1.2
N17776334: CD1.2 CP1.1 CP2.2 LP1.2
N17776576: CP2.1 CP3.2 LP2.2
N17777945: CN2.2 CN3.2 LN2.1

Not connected (* = marked no-connect by the designer): D900 1*; P201 40*; P900 4; RP200 3(R13)* 6(R16)*; U100 C1(RESET#_/_SIO3)*; U204 5(PG)*; U205 5(NC)*

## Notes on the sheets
sheet 1
- Radio Interface
- Radio Interface
- Sub-GHz matching network
- High Frequency Crystal
- SMA Connector
- Thermistor Ground pin
  to be placed close to
  X1 Ground pin.
- Power & Decoupling
- VDD Configuration
- RF Shielding
- Power Config 1
  VMCU to VDD
- Power Config 2
  VLDO_3V6 to VDD
- R210
- Mount
- Not mount
- R211
- Not mount
- Mount
- Overlay
  pads of
  R210/R211
sheet 2
- Board Function
- Page
- Title Page
- 1
- RF & Power
- 2
- Board Power
- 3
- EFR32 Signal Assignments
- 4
- WSTK Connectors & Board ID
- 5
- LEGAL NOTICE:
  SILICON LABORATORIES INC. (“SILICON LABS”) AND/OR ITS LICENSORS DO NOT WARRANT THE ACCURACY
  OR COMPLETENESS OF THIS SCHEMATIC OR ANY INFORMATION CONTAINED WITHIN THIS SCHEMATIC.
  IT IS PROVIDED “AS-IS” FOR REFERENCE ONLY. SILICON LABS DOES NOT WARRANT THAT THIS DESIGN
  WILL MEET THE SPECIFICATIONS,  BE SUITABLE FOR YOUR APPLICATION OR FIT FOR ANY PARTICULAR
  PURPOSE, OR WILL OPERATE IN YOUR IMPLEMENTATION. SILICON LABS AND ITS LICENSORS DO NOT
  WARRANT THAT THE DESIGN IMPLIED IN THIS SCHEMATIC IS PRODUCTION-WORTHY. YOU SHOULD
  COMPLETELY VALIDATE AND TEST YOUR DESIGN IMPLEMENTATION TO CONFIRM SYSTEM FUNCTIONALITY
  FOR YOUR APPLICATION.
sheet 3
- Pin Mapping
- I/O Port Pins
- EFR32 Pin
- EFR32 Peripheral
- EXP Header
  Connection
- WSTK
  Breakout Pin
- WSTK Peripheral
  Connection
- Serial resistors on SPI interface to mitigate any
  signal integrity issues that might arise when an
  unknown load is connected to the expansion header.
- Serial Flash
- Low Frequency Crystal
sheet 4
- Debug USB Connection
- 3.6V Regulator
- VMCU Configuration
- From Board
  USB Conn.
  Board on
  WSTK*
- From WSTK
- Standalone
- R201
- Mount
- Mount
- Not mount
- R202
- Not mount
- Not mount
- Mount
- 3.3V Regulator
- * To supply from the on-board USB connector,
    set the power switch on the WSTK to USB state.
- Overlay
  pads of
  R201/R202
- WSTK Power Decoupling
sheet 5
- WSTK Connectors
- Board Identification
- Test Points
